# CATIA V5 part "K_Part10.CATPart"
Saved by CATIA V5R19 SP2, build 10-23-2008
Part number: Logement_Verin(Squelette)
Publications: "Distance_Inter_Pivot", "Point.1", "Droite_DirectionGlissière", "Droite.1", "Droite.3", "Epaisseur_LogementVérin", "Plan.1"
Bounding box of the stored display mesh (mm): x 4.5 to 14.5, y 0 to 160, z 0 to 10
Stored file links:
  G:\Khaled_CFAO_2011\SIL\SIL_GR1\mneves\Khaled\CAD_CATIA_Modifie\K_Part10.CATPart
  G:\Khaled_CFAO_2011\SIL\SIL_GR1\mneves\Khaled\CAD_CATIA_Modifie\K_SquePince_A_Bois.CATProduct
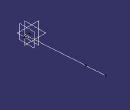
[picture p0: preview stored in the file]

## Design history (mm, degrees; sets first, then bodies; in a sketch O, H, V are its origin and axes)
External parameters (linked from other documents)
  External.Distance_Inter_Pivot = 200 mm
  `External.Epaisseur_LogementVérin` = 10 mm
Set1
  Point1: linked copy from another document
  Line1 "Droite_DirectionGlissière": linked copy from another document
  Plane1: linked copy from another document
Set2
  Line2: type PtDir, RefPoint Point1, Direction Line1, Start 0, End 120 {= External.Distance_Inter_Pivot -External.Distance_Inter_Pivot /2.5}
  Line3: type Normal, RefPoint Point1, RefSkin Plane1, Start -5, End 5 {= `External.Epaisseur_LogementVérin` /2}
Body1 (main body)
